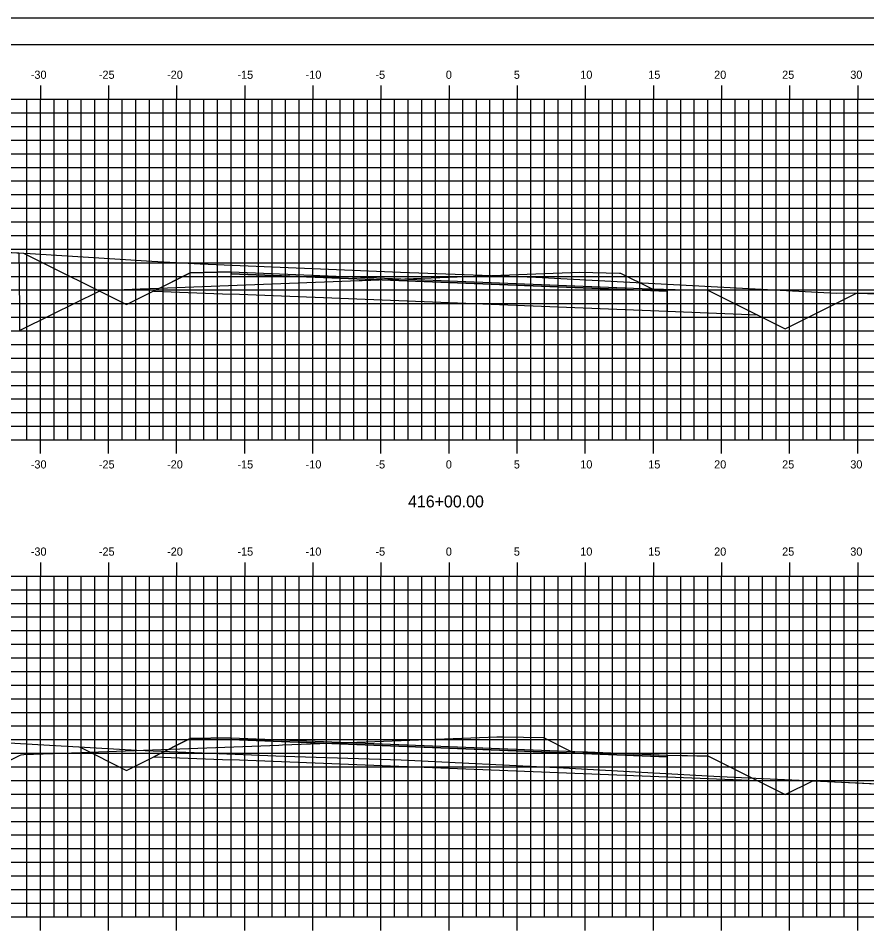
# Model space of a CAD drawing. Extents: x 1168600 to 1177589, y 610178 to 611246.
# Drawn here: x 1172936.2 to 1172998.5, y 610943.3 to 611010.5 of the extents above; entities that cross this region are included whole.
import ezdxf

# ---------------------------------------------------------------- set-up
doc = ezdxf.new("R2010")
doc.units = 0
for name, color, linetype in [('_Construction', 7, 'Continuous'), ('_Station Equation', 7, 'Continuous'), ('D_Roadway_Edge_TW', 7, 'Continuous'), ('D_Roadway_SubGrade', 7, 'Continuous'), ('D_Text_Standard', 7, 'Continuous'), ('DIMENSIONS', 7, 'Continuous'), ('H_V ANNOTATION', 7, 'Continuous'), ('MAJOR', 7, 'Continuous'), ('MATCH LINES', 7, 'Continuous'), ('MINOR', 7, 'Continuous')]:
    doc.layers.add(name, color=color, linetype=linetype)

msp = doc.modelspace()

# ---------------------------------------------------------------- linework, layer by layer
at = {"layer": '_Construction'}
msp.add_line((1173052.828, 611008.596), (1172892.828, 611008.596), dxfattribs=at)
msp.add_lwpolyline([(1172884.735, 610900.537), (1173054.735, 610900.537), (1173054.735, 611010.537), (1172884.735, 611010.537)], close=True, dxfattribs=at)
at = {"layer": '_Station Equation'}
for points in [[(1172897.828, 610997.666), (1172909.229, 610994.519), (1172918.457, 610994.212), (1172937.085, 610993.282), (1172946.015, 610992.72), (1172949.542, 610992.516), (1172964.259, 610991.916), (1172971.598, 610991.641), (1172974.189, 610991.532), (1172996.259, 610990.368), (1172999.917, 610990.376), (1173016.141, 610989.768), (1173018.672, 610989.249), (1173026.012, 610988.574), (1173031.228, 610990.149), (1173037.828, 610992.083)], [(1172933.624, 610993.454), (1172936.248, 610993.323), (1172936.252, 610992.851), (1172936.258, 610992.164), (1172936.291, 610988.234), (1172936.298, 610987.619), (1172938.702, 610988.81), (1172942.097, 610990.493), (1172942.236, 610990.562), (1172945.14, 610990.672), (1172945.253, 610990.677), (1172961.237, 610991.284), (1172961.341, 610991.288), (1172961.437, 610991.292), (1172964.578, 610991.411), (1172977.406, 610991.901), (1172980.327, 610991.838), (1172980.418, 610991.836), (1172982.637, 610990.727), (1172982.729, 610990.681), (1172982.735, 610990.681), (1172982.779, 610990.68), (1172982.807, 610990.679), (1172983.561, 610990.649), (1172983.828, 610990.639), (1172984.391, 610990.627), (1172984.434, 610990.626), (1172985.066, 610990.614), (1172986.828, 610990.579), (1172987.256, 610990.365), (1172992.491, 610987.747), (1172993.529, 610988.266), (1172997.739, 610990.371), (1172997.79, 610990.371), (1172997.79, 610990.371), (1172997.791, 610990.371), (1173016.141, 610989.768)], [(1172897.828, 610961.657), (1172905.864, 610959.53), (1172915.123, 610958.484), (1172918.463, 610958.369), (1172923.968, 610958.025), (1172944.901, 610956.826), (1172955.721, 610956.388), (1172964.308, 610956.113), (1172976.23, 610955.53), (1172987.711, 610954.888), (1172999.865, 610954.329), (1173010.976, 610953.775), (1173015.432, 610953.343), (1173021.291, 610952.8), (1173037.828, 610957.291)], [(1172933.288, 610954.949), (1172936.282, 610956.425), (1172936.409, 610956.487), (1172936.609, 610956.495), (1172939.438, 610956.601), (1172955.324, 610957.195), (1172955.597, 610957.205), (1172961.731, 610957.434), (1172971.326, 610957.792), (1172971.732, 610957.808), (1172971.811, 610957.806), (1172974.754, 610957.741), (1172976.697, 610956.772), (1172976.787, 610956.727), (1172976.793, 610956.727), (1172976.838, 610956.732), (1172976.867, 610956.73), (1172977.636, 610956.7), (1172977.691, 610956.698), (1172977.989, 610956.686), (1172979.111, 610956.641), (1172983.828, 610956.452), (1172986.011, 610956.408), (1172986.828, 610956.392), (1172992.491, 610953.561), (1172994.519, 610954.575), (1172994.569, 610954.572), (1172994.571, 610954.572), (1173010.976, 610953.775)]]:
    msp.add_lwpolyline(points, dxfattribs=at)
at = {"layer": 'D_Roadway_Edge_TW'}
for points in [[(1172951.828, 610991.794), (1172951.828, 610991.919), (1172967.828, 610991.279), (1172983.828, 610990.639), (1172983.828, 610990.514), (1172967.828, 610991.154)], [(1172951.828, 610957.607), (1172951.828, 610957.732), (1172967.828, 610957.092), (1172983.828, 610956.452), (1172983.828, 610956.327), (1172967.828, 610956.967)]]:
    msp.add_lwpolyline(points, close=True, dxfattribs=at)
at = {"layer": 'D_Roadway_SubGrade'}
for points in [[(1172951.828, 610991.919), (1172948.828, 610991.859), (1172946.152, 610990.521), (1172951.828, 610990.294)], [(1172951.828, 610990.294), (1172951.828, 610991.794), (1172967.828, 610991.154), (1172983.828, 610990.514), (1172983.828, 610989.014), (1172967.828, 610989.654)], [(1172983.828, 610990.639), (1172986.828, 610990.579), (1172990.491, 610988.747), (1172983.828, 610989.014)], [(1172951.828, 610957.732), (1172948.828, 610957.672), (1172946.152, 610956.334), (1172951.828, 610956.107)], [(1172951.828, 610956.107), (1172951.828, 610957.607), (1172967.828, 610956.967), (1172983.828, 610956.327), (1172983.828, 610954.827), (1172967.828, 610955.467)], [(1172983.828, 610956.452), (1172986.828, 610956.392), (1172990.491, 610954.561), (1172983.828, 610954.827)]]:
    msp.add_lwpolyline(points, close=True, dxfattribs=at)
at = {"layer": 'D_Text_Standard'}
for points in [[(1172936.579, 610993.307), (1172944.152, 610989.521), (1172948.828, 610991.859), (1172951.828, 610991.919), (1172967.828, 610991.279), (1172983.828, 610990.639), (1172986.828, 610990.579), (1172992.491, 610987.747), (1172997.739, 610990.371)], [(1172940.685, 610957.067), (1172944.152, 610955.334), (1172948.828, 610957.672), (1172951.828, 610957.732), (1172967.828, 610957.092), (1172983.828, 610956.452), (1172986.828, 610956.392), (1172992.491, 610953.561), (1172994.519, 610954.575)]]:
    msp.add_lwpolyline(points, dxfattribs=at)
at = {"layer": 'DIMENSIONS'}
for points in [[(1172951.828, 610991.794), (1172951.828, 610991.794), (1172967.828, 610991.154), (1172983.828, 610990.514), (1172983.828, 610990.514), (1172967.828, 610991.154)], [(1172951.828, 610957.607), (1172951.828, 610957.607), (1172967.828, 610956.967), (1172983.828, 610956.327), (1172983.828, 610956.327), (1172967.828, 610956.967)]]:
    msp.add_lwpolyline(points, close=True, dxfattribs=at)
for points in [[(1172951.828, 610991.794), (1172951.828, 610991.794)], [(1172951.828, 610991.794), (1172951.828, 610991.794)], [(1172983.828, 610990.514), (1172983.828, 610990.514)], [(1172983.828, 610990.514), (1172983.828, 610990.514)], [(1172951.828, 610957.607), (1172951.828, 610957.607)], [(1172951.828, 610957.607), (1172951.828, 610957.607)], [(1172983.828, 610956.327), (1172983.828, 610956.327)], [(1172983.828, 610956.327), (1172983.828, 610956.327)]]:
    msp.add_lwpolyline(points, dxfattribs=at)
at = {"layer": 'MAJOR'}
for p, q in [((1172937.828, 611005.598), (1172937.828, 611004.596)), ((1172942.828, 611005.598), (1172942.828, 611004.596)), ((1172947.828, 611005.598), (1172947.828, 611004.596)), ((1172952.828, 611005.598), (1172952.828, 611004.596)), ((1172957.828, 611005.598), (1172957.828, 611004.596)), ((1172962.828, 611005.598), (1172962.828, 611004.596)), ((1172967.828, 611005.598), (1172967.828, 611004.596)), ((1172972.828, 611005.598), (1172972.828, 611004.596)), ((1172977.828, 611005.598), (1172977.828, 611004.596)), ((1172982.828, 611005.598), (1172982.828, 611004.596)), ((1172987.828, 611005.598), (1172987.828, 611004.596)), ((1172992.828, 611005.598), (1172992.828, 611004.596)), ((1172997.828, 611005.598), (1172997.828, 611004.596)), ((1172897.828, 611004.596), (1173037.828, 611004.596)), ((1172897.828, 611004.596), (1173037.828, 611004.596)), ((1172937.828, 610979.596), (1172937.828, 611004.596)), ((1172942.828, 610979.596), (1172942.828, 611004.596)), ((1172947.828, 610979.596), (1172947.828, 611004.596)), ((1172952.828, 610979.596), (1172952.828, 611004.596)), ((1172957.828, 610979.596), (1172957.828, 611004.596)), ((1172962.828, 610979.596), (1172962.828, 611004.596)), ((1172967.828, 610979.596), (1172967.828, 611004.596)), ((1172972.828, 610979.596), (1172972.828, 611004.596)), ((1172977.828, 610979.596), (1172977.828, 611004.596)), ((1172982.828, 610979.596), (1172982.828, 611004.596)), ((1172987.828, 610979.596), (1172987.828, 611004.596)), ((1172992.828, 610979.596), (1172992.828, 611004.596)), ((1172997.828, 610979.596), (1172997.828, 611004.596)), ((1172897.828, 610999.596), (1173037.828, 610999.596)), ((1172897.828, 610994.596), (1173037.828, 610994.596)), ((1172897.828, 610989.596), (1173037.828, 610989.596)), ((1172897.828, 610984.596), (1173037.828, 610984.596)), ((1172897.828, 610979.596), (1173037.828, 610979.596)), ((1172897.828, 610979.596), (1173037.828, 610979.596)), ((1172937.828, 610978.594), (1172937.828, 610979.596)), ((1172942.828, 610978.594), (1172942.828, 610979.596)), ((1172947.828, 610978.594), (1172947.828, 610979.596)), ((1172952.828, 610978.594), (1172952.828, 610979.596)), ((1172957.828, 610978.594), (1172957.828, 610979.596)), ((1172962.828, 610978.594), (1172962.828, 610979.596)), ((1172967.828, 610978.594), (1172967.828, 610979.596)), ((1172972.828, 610978.594), (1172972.828, 610979.596)), ((1172977.828, 610978.594), (1172977.828, 610979.596)), ((1172982.828, 610978.594), (1172982.828, 610979.596)), ((1172987.828, 610978.594), (1172987.828, 610979.596)), ((1172992.828, 610978.594), (1172992.828, 610979.596)), ((1172997.828, 610978.594), (1172997.828, 610979.596)), ((1172937.828, 610970.598), (1172937.828, 610969.596)), ((1172942.828, 610970.598), (1172942.828, 610969.596)), ((1172947.828, 610970.598), (1172947.828, 610969.596)), ((1172952.828, 610970.598), (1172952.828, 610969.596)), ((1172957.828, 610970.598), (1172957.828, 610969.596)), ((1172962.828, 610970.598), (1172962.828, 610969.596)), ((1172967.828, 610970.598), (1172967.828, 610969.596)), ((1172972.828, 610970.598), (1172972.828, 610969.596)), ((1172977.828, 610970.598), (1172977.828, 610969.596)), ((1172982.828, 610970.598), (1172982.828, 610969.596)), ((1172987.828, 610970.598), (1172987.828, 610969.596)), ((1172992.828, 610970.598), (1172992.828, 610969.596)), ((1172997.828, 610970.598), (1172997.828, 610969.596)), ((1172897.828, 610969.596), (1173037.828, 610969.596)), ((1172897.828, 610969.596), (1173037.828, 610969.596)), ((1172937.828, 610944.596), (1172937.828, 610969.596)), ((1172942.828, 610944.596), (1172942.828, 610969.596)), ((1172947.828, 610944.596), (1172947.828, 610969.596)), ((1172952.828, 610944.596), (1172952.828, 610969.596)), ((1172957.828, 610944.596), (1172957.828, 610969.596)), ((1172962.828, 610944.596), (1172962.828, 610969.596)), ((1172967.828, 610944.596), (1172967.828, 610969.596)), ((1172972.828, 610944.596), (1172972.828, 610969.596)), ((1172977.828, 610944.596), (1172977.828, 610969.596)), ((1172982.828, 610944.596), (1172982.828, 610969.596)), ((1172987.828, 610944.596), (1172987.828, 610969.596)), ((1172992.828, 610944.596), (1172992.828, 610969.596)), ((1172997.828, 610944.596), (1172997.828, 610969.596)), ((1172897.828, 610964.596), (1173037.828, 610964.596)), ((1172897.828, 610959.596), (1173037.828, 610959.596)), ((1172897.828, 610954.596), (1173037.828, 610954.596)), ((1172897.828, 610949.596), (1173037.828, 610949.596)), ((1172897.828, 610944.596), (1173037.828, 610944.596)), ((1172897.828, 610944.596), (1173037.828, 610944.596)), ((1172937.828, 610943.594), (1172937.828, 610944.596)), ((1172942.828, 610943.594), (1172942.828, 610944.596)), ((1172947.828, 610943.594), (1172947.828, 610944.596)), ((1172952.828, 610943.594), (1172952.828, 610944.596)), ((1172957.828, 610943.594), (1172957.828, 610944.596)), ((1172962.828, 610943.594), (1172962.828, 610944.596)), ((1172967.828, 610943.594), (1172967.828, 610944.596)), ((1172972.828, 610943.594), (1172972.828, 610944.596)), ((1172977.828, 610943.594), (1172977.828, 610944.596)), ((1172982.828, 610943.594), (1172982.828, 610944.596)), ((1172987.828, 610943.594), (1172987.828, 610944.596)), ((1172992.828, 610943.594), (1172992.828, 610944.596)), ((1172997.828, 610943.594), (1172997.828, 610944.596))]:
    msp.add_line(p, q, dxfattribs=at)
at = {"layer": 'MATCH LINES'}
for points in [[(1172951.828, 610991.919), (1172951.828, 610991.794)], [(1172983.828, 610990.639), (1172983.828, 610990.514)], [(1172951.828, 610957.732), (1172951.828, 610957.607)], [(1172983.828, 610956.452), (1172983.828, 610956.327)]]:
    msp.add_lwpolyline(points, dxfattribs=at)
at = {"layer": 'MINOR'}
for p, q in [((1172936.828, 610979.596), (1172936.828, 611004.596)), ((1172938.828, 610979.596), (1172938.828, 611004.596)), ((1172939.828, 610979.596), (1172939.828, 611004.596)), ((1172940.828, 610979.596), (1172940.828, 611004.596)), ((1172941.828, 610979.596), (1172941.828, 611004.596)), ((1172943.828, 610979.596), (1172943.828, 611004.596)), ((1172944.828, 610979.596), (1172944.828, 611004.596)), ((1172945.828, 610979.596), (1172945.828, 611004.596)), ((1172946.828, 610979.596), (1172946.828, 611004.596)), ((1172948.828, 610979.596), (1172948.828, 611004.596)), ((1172949.828, 610979.596), (1172949.828, 611004.596)), ((1172950.828, 610979.596), (1172950.828, 611004.596)), ((1172951.828, 610979.596), (1172951.828, 611004.596)), ((1172953.828, 610979.596), (1172953.828, 611004.596)), ((1172954.828, 610979.596), (1172954.828, 611004.596)), ((1172955.828, 610979.596), (1172955.828, 611004.596)), ((1172956.828, 610979.596), (1172956.828, 611004.596)), ((1172958.828, 610979.596), (1172958.828, 611004.596)), ((1172959.828, 610979.596), (1172959.828, 611004.596)), ((1172960.828, 610979.596), (1172960.828, 611004.596)), ((1172961.828, 610979.596), (1172961.828, 611004.596)), ((1172963.828, 610979.596), (1172963.828, 611004.596)), ((1172964.828, 610979.596), (1172964.828, 611004.596)), ((1172965.828, 610979.596), (1172965.828, 611004.596)), ((1172966.828, 610979.596), (1172966.828, 611004.596)), ((1172968.828, 610979.596), (1172968.828, 611004.596)), ((1172969.828, 610979.596), (1172969.828, 611004.596)), ((1172970.828, 610979.596), (1172970.828, 611004.596)), ((1172971.828, 610979.596), (1172971.828, 611004.596)), ((1172973.828, 610979.596), (1172973.828, 611004.596)), ((1172974.828, 610979.596), (1172974.828, 611004.596)), ((1172975.828, 610979.596), (1172975.828, 611004.596)), ((1172976.828, 610979.596), (1172976.828, 611004.596)), ((1172978.828, 610979.596), (1172978.828, 611004.596)), ((1172979.828, 610979.596), (1172979.828, 611004.596)), ((1172980.828, 610979.596), (1172980.828, 611004.596)), ((1172981.828, 610979.596), (1172981.828, 611004.596)), ((1172983.828, 610979.596), (1172983.828, 611004.596)), ((1172984.828, 610979.596), (1172984.828, 611004.596)), ((1172985.828, 610979.596), (1172985.828, 611004.596)), ((1172986.828, 610979.596), (1172986.828, 611004.596)), ((1172988.828, 610979.596), (1172988.828, 611004.596)), ((1172989.828, 610979.596), (1172989.828, 611004.596)), ((1172990.828, 610979.596), (1172990.828, 611004.596)), ((1172991.828, 610979.596), (1172991.828, 611004.596)), ((1172993.828, 610979.596), (1172993.828, 611004.596)), ((1172994.828, 610979.596), (1172994.828, 611004.596)), ((1172995.828, 610979.596), (1172995.828, 611004.596)), ((1172996.828, 610979.596), (1172996.828, 611004.596)), ((1172897.828, 611003.596), (1173037.828, 611003.596)), ((1172897.828, 611002.596), (1173037.828, 611002.596)), ((1172897.828, 611001.596), (1173037.828, 611001.596)), ((1172897.828, 611000.596), (1173037.828, 611000.596)), ((1172897.828, 610998.596), (1173037.828, 610998.596)), ((1172897.828, 610997.596), (1173037.828, 610997.596)), ((1172897.828, 610996.596), (1173037.828, 610996.596)), ((1172897.828, 610995.596), (1173037.828, 610995.596)), ((1172897.828, 610993.596), (1173037.828, 610993.596)), ((1172897.828, 610992.596), (1173037.828, 610992.596)), ((1172897.828, 610991.596), (1173037.828, 610991.596)), ((1172897.828, 610990.596), (1173037.828, 610990.596)), ((1172897.828, 610988.596), (1173037.828, 610988.596)), ((1172897.828, 610987.596), (1173037.828, 610987.596)), ((1172897.828, 610986.596), (1173037.828, 610986.596)), ((1172897.828, 610985.596), (1173037.828, 610985.596)), ((1172897.828, 610983.596), (1173037.828, 610983.596)), ((1172897.828, 610982.596), (1173037.828, 610982.596)), ((1172897.828, 610981.596), (1173037.828, 610981.596)), ((1172897.828, 610980.596), (1173037.828, 610980.596)), ((1172936.828, 610944.596), (1172936.828, 610969.596)), ((1172938.828, 610944.596), (1172938.828, 610969.596)), ((1172939.828, 610944.596), (1172939.828, 610969.596)), ((1172940.828, 610944.596), (1172940.828, 610969.596)), ((1172941.828, 610944.596), (1172941.828, 610969.596)), ((1172943.828, 610944.596), (1172943.828, 610969.596)), ((1172944.828, 610944.596), (1172944.828, 610969.596)), ((1172945.828, 610944.596), (1172945.828, 610969.596)), ((1172946.828, 610944.596), (1172946.828, 610969.596)), ((1172948.828, 610944.596), (1172948.828, 610969.596)), ((1172949.828, 610944.596), (1172949.828, 610969.596)), ((1172950.828, 610944.596), (1172950.828, 610969.596)), ((1172951.828, 610944.596), (1172951.828, 610969.596)), ((1172953.828, 610944.596), (1172953.828, 610969.596)), ((1172954.828, 610944.596), (1172954.828, 610969.596)), ((1172955.828, 610944.596), (1172955.828, 610969.596)), ((1172956.828, 610944.596), (1172956.828, 610969.596)), ((1172958.828, 610944.596), (1172958.828, 610969.596)), ((1172959.828, 610944.596), (1172959.828, 610969.596)), ((1172960.828, 610944.596), (1172960.828, 610969.596)), ((1172961.828, 610944.596), (1172961.828, 610969.596)), ((1172963.828, 610944.596), (1172963.828, 610969.596)), ((1172964.828, 610944.596), (1172964.828, 610969.596)), ((1172965.828, 610944.596), (1172965.828, 610969.596)), ((1172966.828, 610944.596), (1172966.828, 610969.596)), ((1172968.828, 610944.596), (1172968.828, 610969.596)), ((1172969.828, 610944.596), (1172969.828, 610969.596)), ((1172970.828, 610944.596), (1172970.828, 610969.596)), ((1172971.828, 610944.596), (1172971.828, 610969.596)), ((1172973.828, 610944.596), (1172973.828, 610969.596)), ((1172974.828, 610944.596), (1172974.828, 610969.596)), ((1172975.828, 610944.596), (1172975.828, 610969.596)), ((1172976.828, 610944.596), (1172976.828, 610969.596)), ((1172978.828, 610944.596), (1172978.828, 610969.596)), ((1172979.828, 610944.596), (1172979.828, 610969.596)), ((1172980.828, 610944.596), (1172980.828, 610969.596)), ((1172981.828, 610944.596), (1172981.828, 610969.596)), ((1172983.828, 610944.596), (1172983.828, 610969.596)), ((1172984.828, 610944.596), (1172984.828, 610969.596)), ((1172985.828, 610944.596), (1172985.828, 610969.596)), ((1172986.828, 610944.596), (1172986.828, 610969.596)), ((1172988.828, 610944.596), (1172988.828, 610969.596)), ((1172989.828, 610944.596), (1172989.828, 610969.596)), ((1172990.828, 610944.596), (1172990.828, 610969.596)), ((1172991.828, 610944.596), (1172991.828, 610969.596)), ((1172993.828, 610944.596), (1172993.828, 610969.596)), ((1172994.828, 610944.596), (1172994.828, 610969.596)), ((1172995.828, 610944.596), (1172995.828, 610969.596)), ((1172996.828, 610944.596), (1172996.828, 610969.596)), ((1172897.828, 610968.596), (1173037.828, 610968.596)), ((1172897.828, 610967.596), (1173037.828, 610967.596)), ((1172897.828, 610966.596), (1173037.828, 610966.596)), ((1172897.828, 610965.596), (1173037.828, 610965.596)), ((1172897.828, 610963.596), (1173037.828, 610963.596)), ((1172897.828, 610962.596), (1173037.828, 610962.596)), ((1172897.828, 610961.596), (1173037.828, 610961.596)), ((1172897.828, 610960.596), (1173037.828, 610960.596)), ((1172897.828, 610958.596), (1173037.828, 610958.596)), ((1172897.828, 610957.596), (1173037.828, 610957.596)), ((1172897.828, 610956.596), (1173037.828, 610956.596)), ((1172897.828, 610955.596), (1173037.828, 610955.596)), ((1172897.828, 610953.596), (1173037.828, 610953.596)), ((1172897.828, 610952.596), (1173037.828, 610952.596)), ((1172897.828, 610951.596), (1173037.828, 610951.596)), ((1172897.828, 610950.596), (1173037.828, 610950.596)), ((1172897.828, 610948.596), (1173037.828, 610948.596)), ((1172897.828, 610947.596), (1173037.828, 610947.596)), ((1172897.828, 610946.596), (1173037.828, 610946.596)), ((1172897.828, 610945.596), (1173037.828, 610945.596))]:
    msp.add_line(p, q, dxfattribs=at)

# ---------------------------------------------------------------- texts
at = {"layer": 'H_V ANNOTATION'}
for s, height, p in [('-30', 0.6, (1172937.116, 611006.096)), ('-25', 0.6, (1172942.113, 611006.096)), ('-20', 0.6, (1172947.121, 611006.096)), ('-15', 0.6, (1172952.285, 611006.096)), ('-10', 0.6, (1172957.293, 611006.096)), ('-5', 0.6, (1172962.418, 611006.096)), ('0', 0.6, (1172967.587, 611006.096)), ('5', 0.6, (1172972.579, 611006.096)), ('10', 0.6, (1172977.453, 611006.096)), ('15', 0.6, (1172982.445, 611006.096)), ('20', 0.6, (1172987.282, 611006.096)), ('25', 0.6, (1172992.274, 611006.096)), ('30', 0.6, (1172997.276, 611006.096)), ('-30', 0.6, (1172937.116, 610977.496)), ('-25', 0.6, (1172942.113, 610977.496)), ('-20', 0.6, (1172947.121, 610977.496)), ('-15', 0.6, (1172952.285, 610977.496)), ('-10', 0.6, (1172957.293, 610977.496)), ('-5', 0.6, (1172962.418, 610977.496)), ('0', 0.6, (1172967.587, 610977.496)), ('5', 0.6, (1172972.579, 610977.496)), ('10', 0.6, (1172977.453, 610977.496)), ('15', 0.6, (1172982.445, 610977.496)), ('20', 0.6, (1172987.282, 610977.496)), ('25', 0.6, (1172992.274, 610977.496)), ('30', 0.6, (1172997.276, 610977.496)), ('416+00.00', 0.875, (1172964.816, 610974.639)), ('-30', 0.6, (1172937.116, 610971.096)), ('-25', 0.6, (1172942.113, 610971.096)), ('-20', 0.6, (1172947.121, 610971.096)), ('-15', 0.6, (1172952.285, 610971.096)), ('-10', 0.6, (1172957.293, 610971.096)), ('-5', 0.6, (1172962.418, 610971.096)), ('0', 0.6, (1172967.587, 610971.096)), ('5', 0.6, (1172972.579, 610971.096)), ('10', 0.6, (1172977.453, 610971.096)), ('15', 0.6, (1172982.445, 610971.096)), ('20', 0.6, (1172987.282, 610971.096)), ('25', 0.6, (1172992.274, 610971.096)), ('30', 0.6, (1172997.276, 610971.096))]:
    msp.add_text(s, height=height, dxfattribs=at).set_placement(p)

doc.saveas('drawing.dxf')
